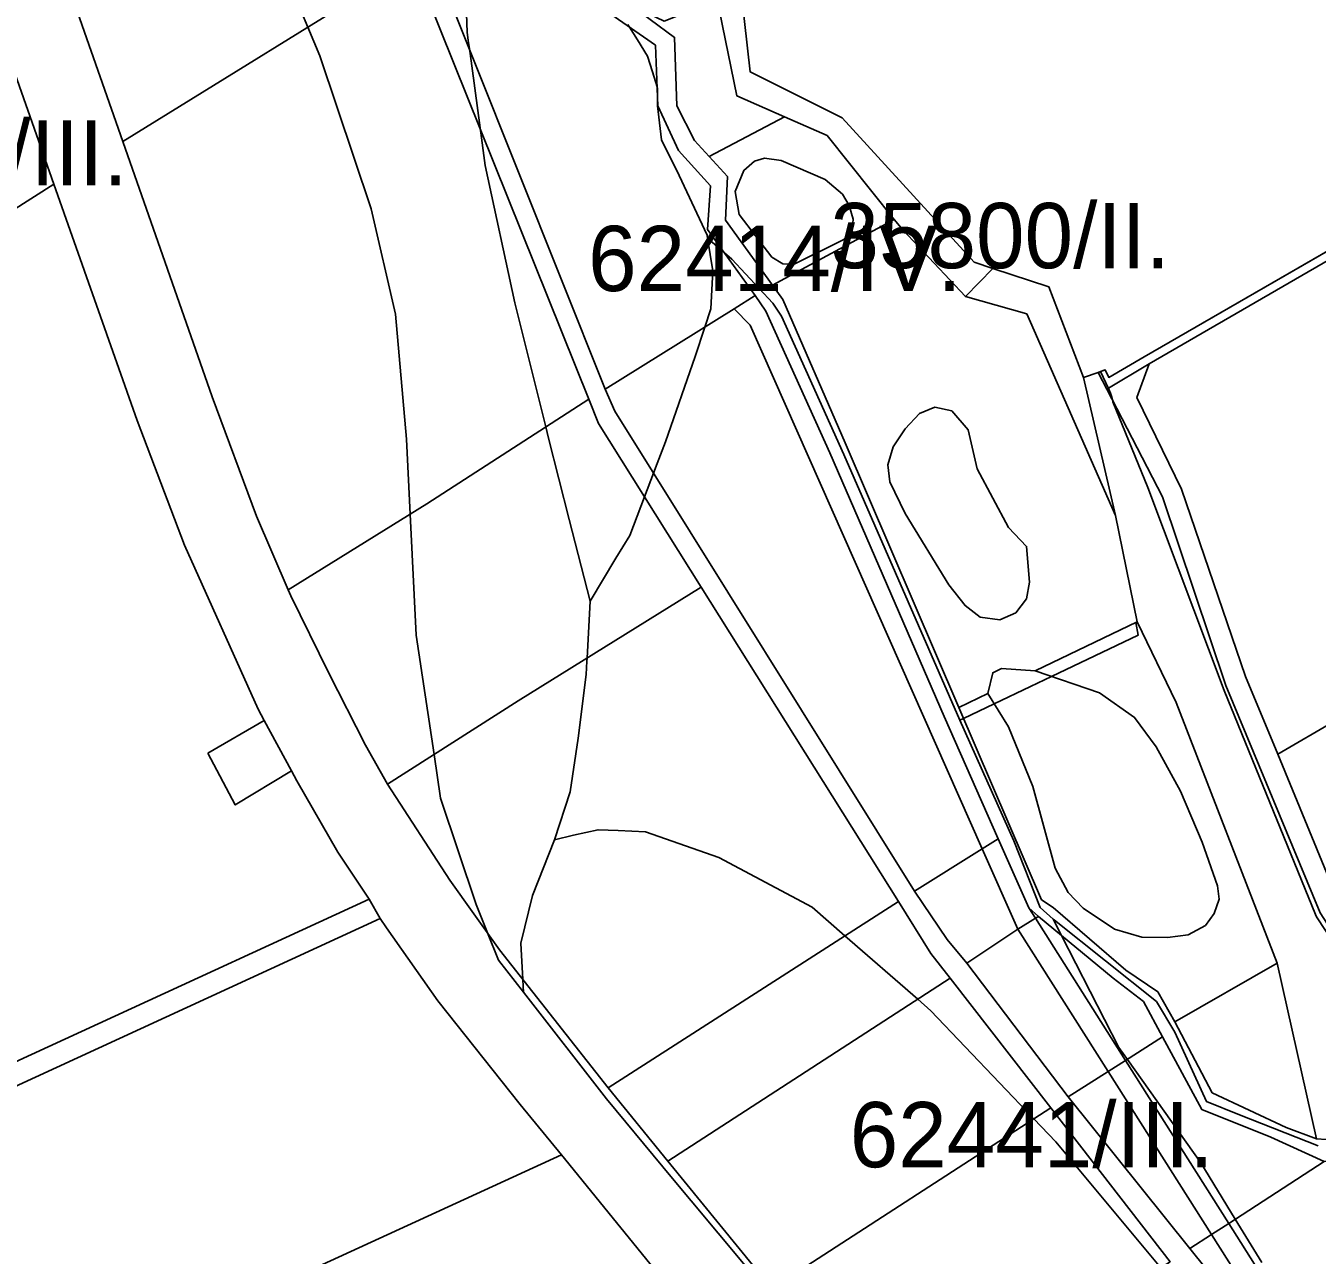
# Model space of a CAD drawing. Extents: x -522079 to -518792, y -1142400 to -1139961.
# Drawn here: x -520985.3 to -520688.5, y -1140520.9 to -1140238.4 of the extents above; entities that cross this region are included whole.
import ezdxf

# ---------------------------------------------------------------- set-up
doc = ezdxf.new("R2010")
doc.units = 0
for name, color, linetype in [('Hranice parcel', 7, 'Continuous'), ('Parcelní čísla', 7, 'Continuous'), ('Poz předměty', 7, 'Continuous'), ('Vnitřní kresba', 7, 'Continuous'), ('Značky bodu BP', 7, 'Continuous'), ('Značky budov', 7, 'Continuous')]:
    doc.layers.add(name, color=color, linetype=linetype)

msp = doc.modelspace()

# ---------------------------------------------------------------- linework, layer by layer
at = {"layer": 'Hranice parcel'}
for points in [[(-520489.41, -1140176.97), (-520610.57, -1140248.68), (-520727.12, -1140316.09), (-520736.79, -1140321.94), (-520738.8, -1140318.04), (-520737.2, -1140317.47), (-520736.37, -1140319.22), (-520728.21, -1140314.51), (-520611.62, -1140247.2), (-520491.09, -1140175.17)], [(-520989.57, -1140189.1), (-520981.4, -1140212.45), (-520975.5, -1140229.32), (-520963.03, -1140264.99), (-520942.5, -1140323.7), (-520932.27, -1140351.12), (-520925.04, -1140368.05), (-520924.44, -1140369.44), (-520915.77, -1140387.04), (-520907.24, -1140403.74), (-520902.19, -1140412.67), (-520887.82, -1140434.78), (-520876.46, -1140450.75), (-520851.49, -1140482.48), (-520837.71, -1140499.35), (-520813.81, -1140528.62)], [(-520765.71, -1140616.57), (-520862.22, -1140497.87), (-520871.65, -1140486.28), (-520890.58, -1140462.46), (-520902.4, -1140445.74), (-520903.84, -1140443.54), (-520906.37, -1140439.12), (-520913.58, -1140428.33), (-520923.06, -1140411.9), (-520924.28, -1140409.64), (-520930.52, -1140398.04), (-520931.92, -1140395.43), (-520948.85, -1140357.77), (-520959.74, -1140329.07), (-520978.89, -1140274.79), (-520991.34, -1140239.5)], [(-520560.63, -1140549.81), (-520611.7, -1140490.5), (-520625.05, -1140483.49), (-520666, -1140475.86), (-520687.78, -1140442.24), (-520709.46, -1140390.03), (-520724.04, -1140346.68), (-520736.79, -1140321.94), (-520727.12, -1140316.09), (-520729.96, -1140323.84), (-520719.64, -1140344.89), (-520704.93, -1140387.92), (-520697.54, -1140405.82), (-520683.48, -1140439.85), (-520673.87, -1140455.8), (-520666.98, -1140467.24), (-520659.41, -1140472.47), (-520623.97, -1140478.75), (-520608.7, -1140486.32), (-520592.52, -1140504.62), (-520587.65, -1140510.13), (-520562.49, -1140540.48)]]:
    msp.add_lwpolyline(points, dxfattribs=at)
for points in [[(-520822.46, -1140303.46), (-520817.67, -1140300.36), (-520815.23, -1140303.96), (-520800.48, -1140336.51), (-520774.21, -1140397.13), (-520761.78, -1140425.25), (-520765.49, -1140427.57), (-520818.84, -1140307.19)], [(-520943.46, -1140405.56), (-520930.52, -1140398.04), (-520924.28, -1140409.64), (-520937.19, -1140417.44)], [(-520754.76, -1140441.12), (-520753.24, -1140443.52), (-520757.32, -1140446.02), (-520765.49, -1140427.57), (-520761.78, -1140425.25)], [(-521428.47, -1140683.93), (-521438.02, -1140688.47), (-521441.99, -1140684.63), (-521355.48, -1140644.9), (-521309.07, -1140623.96), (-521152, -1140551.52), (-521060.49, -1140509.3), (-521045.09, -1140502.65), (-521031.07, -1140496.4), (-520906.37, -1140439.12), (-520903.84, -1140443.54), (-521038.29, -1140505.39), (-521174.07, -1140567.72), (-521187.8, -1140573.75), (-521306.81, -1140628.37)], [(-520757.32, -1140446.02), (-520753.24, -1140443.52), (-520732.54, -1140476.21), (-520736.54, -1140478.75)], [(-520721.21, -1140467.33), (-520697.67, -1140453.81), (-520688.63, -1140494.17), (-520695.64, -1140491.57), (-520712.6, -1140483.62)], [(-520732.54, -1140476.21), (-520708.82, -1140513.67), (-520712.75, -1140516.21), (-520736.54, -1140478.75)], [(-520708.82, -1140513.67), (-520688.32, -1140546.05), (-520692.27, -1140548.47), (-520712.75, -1140516.21)]]:
    msp.add_lwpolyline(points, close=True, dxfattribs=at)
at = {"layer": 'Parcelní čísla'}
for points in [[(-520697.54, -1140405.82), (-520704.93, -1140387.92), (-520719.64, -1140344.89), (-520729.96, -1140323.84), (-520727.12, -1140316.09), (-520610.57, -1140248.68), (-520489.41, -1140176.97), (-520443.64, -1140149.48), (-520437.53, -1140151.12), (-520407.86, -1140236.34), (-520563.45, -1140327.62)], [(-520896.25, -1140223.69), (-520963.03, -1140264.99), (-520975.5, -1140229.32), (-520909.48, -1140190.7)], [(-520863.77, -1140204.01), (-520859.87, -1140225.61), (-520850.88, -1140235.71), (-520840.6, -1140242.88), (-520840.04, -1140256.81), (-520835.3, -1140267.04), (-520827.93, -1140275.18), (-520828.6, -1140285.19), (-520817.67, -1140300.36), (-520822.46, -1140303.46), (-520852.13, -1140321.93), (-520892.27, -1140221.28)], [(-520963.03, -1140264.99), (-520896.25, -1140223.69), (-520855.89, -1140324.19), (-520893.13, -1140348.26), (-520925.04, -1140368.05), (-520932.27, -1140351.12), (-520942.5, -1140323.7)], [(-520407.86, -1140236.34), (-520389.24, -1140289.48), (-520535.21, -1140374.77), (-520673.87, -1140455.8), (-520683.48, -1140439.85), (-520697.54, -1140405.82), (-520563.45, -1140327.62)], [(-521144.75, -1140380.49), (-521166.55, -1140356.84), (-521138.04, -1140336), (-521105.44, -1140313.39), (-521071.25, -1140292.13), (-521029.36, -1140265.01), (-520991.34, -1140239.5), (-520978.89, -1140274.79)], [(-520943.46, -1140405.56), (-520937.19, -1140417.44), (-520924.28, -1140409.64), (-520923.06, -1140411.9), (-520913.58, -1140428.33), (-520906.37, -1140439.12), (-521031.07, -1140496.4), (-521039.03, -1140495.22), (-521144.75, -1140380.49), (-520978.89, -1140274.79), (-520959.74, -1140329.07), (-520948.85, -1140357.77), (-520931.92, -1140395.43), (-520930.52, -1140398.04)], [(-520853.68, -1140329.78), (-520830.07, -1140367.42), (-520872.15, -1140393.54), (-520902.19, -1140412.67), (-520907.24, -1140403.74), (-520915.77, -1140387.04), (-520924.44, -1140369.44), (-520925.04, -1140368.05), (-520893.13, -1140348.26), (-520855.89, -1140324.19)], [(-520781.06, -1140437.3), (-520765.49, -1140427.57), (-520757.32, -1140446.02), (-520769.04, -1140453.82), (-520773.55, -1140448.4)], [(-520851.49, -1140482.48), (-520784.75, -1140439.67), (-520777.25, -1140451.62), (-520772.84, -1140457.31), (-520837.71, -1140499.35)], [(-521174.07, -1140567.72), (-521038.29, -1140505.39), (-520903.84, -1140443.54), (-520902.4, -1140445.74), (-520890.58, -1140462.46), (-520871.65, -1140486.28), (-520862.22, -1140497.87), (-521134.28, -1140622.71), (-521175.11, -1140573.76)], [(-520757.32, -1140446.02), (-520736.54, -1140478.75), (-520745.68, -1140484.57), (-520769.04, -1140453.82)], [(-520837.71, -1140499.35), (-520772.84, -1140457.31), (-520749.72, -1140487.1), (-520813.81, -1140528.62)], [(-520736.54, -1140478.75), (-520712.75, -1140516.21), (-520717.71, -1140519.42), (-520745.68, -1140484.57)], [(-520785.9, -1140562.81), (-520813.81, -1140528.62), (-520749.72, -1140487.1), (-520722.28, -1140522.46), (-520735.82, -1140531.09)], [(-520862.22, -1140497.87), (-520765.71, -1140616.57), (-520897.82, -1140676.39), (-521036.95, -1140739.4), (-521134.28, -1140622.71)], [(-520712.75, -1140516.21), (-520692.27, -1140548.47), (-520693.7, -1140549.35), (-520717.71, -1140519.42)]]:
    msp.add_lwpolyline(points, close=True, dxfattribs=at)
msp.add_lwpolyline([(-520722.28, -1140522.46), (-520749.72, -1140487.1), (-520772.84, -1140457.31), (-520777.25, -1140451.62), (-520784.75, -1140439.67), (-520830.07, -1140367.42), (-520853.68, -1140329.78), (-520855.89, -1140324.19), (-520896.25, -1140223.69), (-520909.48, -1140190.7), (-520905.41, -1140188.32), (-520892.27, -1140221.28), (-520852.13, -1140321.93), (-520849.95, -1140326.96), (-520781.06, -1140437.3), (-520773.55, -1140448.4), (-520769.04, -1140453.82), (-520745.68, -1140484.57), (-520717.71, -1140519.42), (-520693.7, -1140549.35)], dxfattribs=at)
at = {"layer": 'Poz předměty'}
for points in [[(-520831.58, -1140264.76), (-520835.7, -1140256.78), (-520836.21, -1140241.05), (-520847.4, -1140232.82), (-520856.59, -1140222.67), (-520843.85, -1140234.81), (-520838.62, -1140237.3), (-520834.17, -1140235.54), (-520832.49, -1140233.14), (-520829.57, -1140196.57), (-520831.74, -1140193.15), (-520834.84, -1140193.48), (-520857.8, -1140202.58), (-520859.91, -1140204.51), (-520858.48, -1140201.26), (-520811.93, -1140174.77), (-520818.11, -1140203.91), (-520825.87, -1140235.03), (-520821.91, -1140254.48), (-520810.93, -1140259.32), (-520828.22, -1140268.46)], [(-520828.22, -1140268.46), (-520810.93, -1140259.32), (-520801.15, -1140263.64), (-520785.74, -1140282.9), (-520813.67, -1140297.99), (-520824.45, -1140283.03), (-520824.03, -1140273.06)], [(-520817.84, -1140269.53), (-520820.3, -1140271.64), (-520822.29, -1140276.46), (-520821.31, -1140281.75), (-520813.83, -1140291.57), (-520811.29, -1140293.11), (-520808.84, -1140293.29), (-520797.46, -1140287.61), (-520795.38, -1140285.61), (-520795.15, -1140282.87), (-520796.05, -1140279.66), (-520797.56, -1140277.1), (-520801.58, -1140273.72), (-520811.67, -1140269.37), (-520815.5, -1140268.8)], [(-520783.73, -1140285.25), (-520769.34, -1140300.61), (-520755.22, -1140304.57), (-520734.8, -1140350.95), (-520729.88, -1140375.38), (-520753.32, -1140386.65), (-520761.05, -1140386.08), (-520763.05, -1140387.08), (-520764.21, -1140391.88), (-520770.87, -1140395.08), (-520797.01, -1140334.21), (-520811.33, -1140301.33), (-520813.67, -1140297.99), (-520785.74, -1140282.9)], [(-520754.64, -1140366.29), (-520755.29, -1140358.03), (-520759.43, -1140353.7), (-520766.65, -1140340.21), (-520768.74, -1140331.28), (-520772.48, -1140326.88), (-520776.36, -1140326.07), (-520779.88, -1140327.47), (-520783.19, -1140331.06), (-520785.95, -1140335.16), (-520787.17, -1140339.26), (-520786.73, -1140343.23), (-520783.16, -1140350.46), (-520773.17, -1140366.91), (-520769.43, -1140371.66), (-520765.93, -1140374.29), (-520761.4, -1140374.89), (-520757.78, -1140373.33), (-520755.28, -1140370.09)], [(-520752.54, -1140443.09), (-520753.24, -1140443.52), (-520754.76, -1140441.12)], [(-520735.34, -1140457.3), (-520728.4, -1140462.65), (-520724, -1140470.78), (-520732.54, -1140476.21), (-520753.24, -1140443.52), (-520752.54, -1140443.09)], [(-520732.54, -1140476.21), (-520724, -1140470.78), (-520714.97, -1140487.48), (-520699.14, -1140493.81), (-520686.89, -1140499.45), (-520708.82, -1140513.67)], [(-520686.89, -1140499.45), (-520675.92, -1140498.77), (-520661.91, -1140491.42), (-520635.69, -1140488.94), (-520617.72, -1140496.63), (-520614.24, -1140500.69), (-520688.32, -1140546.05), (-520708.82, -1140513.67)]]:
    msp.add_lwpolyline(points, close=True, dxfattribs=at)
at = {"layer": 'Vnitřní kresba'}
for points in [[(-520821.47, -1140225.09), (-520818.83, -1140248.97), (-520797.63, -1140259.52), (-520767.33, -1140292.73), (-520763.01, -1140294.16), (-520769.34, -1140300.61), (-520783.73, -1140285.25), (-520785.74, -1140282.9), (-520801.15, -1140263.64), (-520810.93, -1140259.32), (-520821.91, -1140254.48), (-520825.87, -1140235.03)], [(-520847.4, -1140232.82), (-520836.21, -1140241.05), (-520835.7, -1140256.78), (-520831.58, -1140264.76), (-520828.22, -1140268.46), (-520824.03, -1140273.06), (-520824.45, -1140283.03), (-520813.67, -1140297.99), (-520811.33, -1140301.33), (-520797.01, -1140334.21), (-520770.87, -1140395.08), (-520751.81, -1140439.25), (-520749.19, -1140441.04), (-520732.44, -1140455.44), (-520725.07, -1140460.42), (-520721.21, -1140467.33), (-520712.6, -1140483.62), (-520695.64, -1140491.57), (-520688.63, -1140494.17), (-520677.55, -1140494.96)], [(-520686.89, -1140499.45), (-520699.14, -1140493.81), (-520714.97, -1140487.48), (-520724, -1140470.78), (-520728.4, -1140462.65), (-520735.34, -1140457.3), (-520752.54, -1140443.09), (-520754.76, -1140441.12), (-520761.78, -1140425.25), (-520774.21, -1140397.13), (-520800.48, -1140336.51), (-520815.23, -1140303.96), (-520817.67, -1140300.36), (-520828.6, -1140285.19), (-520827.93, -1140275.18), (-520835.3, -1140267.04), (-520840.04, -1140256.81), (-520840.6, -1140242.88), (-520850.88, -1140235.71)], [(-520677.55, -1140494.96), (-520688.63, -1140494.17), (-520697.67, -1140453.81), (-520720.9, -1140393.9), (-520729.88, -1140375.38), (-520734.8, -1140350.95), (-520755.22, -1140304.57), (-520769.34, -1140300.61), (-520763.01, -1140294.16), (-520750.13, -1140298.42), (-520742.16, -1140319.24), (-520738.8, -1140318.04), (-520736.79, -1140321.94), (-520724.04, -1140346.68), (-520709.46, -1140390.03), (-520687.78, -1140442.24)]]:
    msp.add_lwpolyline(points, dxfattribs=at)
for points in [[(-520795.15, -1140282.87), (-520795.38, -1140285.61), (-520797.46, -1140287.61), (-520808.84, -1140293.29), (-520811.29, -1140293.11), (-520813.83, -1140291.57), (-520821.31, -1140281.75), (-520822.29, -1140276.46), (-520820.3, -1140271.64), (-520817.84, -1140269.53), (-520815.5, -1140268.8), (-520811.67, -1140269.37), (-520801.58, -1140273.72), (-520797.56, -1140277.1), (-520796.05, -1140279.66)], [(-520768.74, -1140331.28), (-520766.65, -1140340.21), (-520759.43, -1140353.7), (-520755.29, -1140358.03), (-520754.64, -1140366.29), (-520755.28, -1140370.09), (-520757.78, -1140373.33), (-520761.4, -1140374.89), (-520765.93, -1140374.29), (-520769.43, -1140371.66), (-520773.17, -1140366.91), (-520783.16, -1140350.46), (-520786.73, -1140343.23), (-520787.17, -1140339.26), (-520785.95, -1140335.16), (-520783.19, -1140331.06), (-520779.88, -1140327.47), (-520776.36, -1140326.07), (-520772.48, -1140326.88)], [(-520729.88, -1140375.38), (-520720.9, -1140393.9), (-520697.67, -1140453.81), (-520721.21, -1140467.33), (-520725.07, -1140460.42), (-520732.44, -1140455.44), (-520749.19, -1140441.04), (-520751.81, -1140439.25), (-520770.87, -1140395.08), (-520764.21, -1140391.88), (-520759.4, -1140399.48), (-520753.83, -1140413.22), (-520748.72, -1140432.03), (-520745.71, -1140437.58), (-520742.3, -1140441.21), (-520735.07, -1140445.99), (-520728.76, -1140447.85), (-520722.88, -1140447.92), (-520718.16, -1140447.28), (-520714.17, -1140445.14), (-520712.14, -1140442.41), (-520711.04, -1140439.09), (-520711.41, -1140436.09), (-520714.9, -1140426), (-520719.87, -1140414.3), (-520725.51, -1140404.14), (-520730.43, -1140397.36), (-520738.54, -1140391.69), (-520753.32, -1140386.65)], [(-520753.32, -1140386.65), (-520738.54, -1140391.69), (-520730.43, -1140397.36), (-520725.51, -1140404.14), (-520719.87, -1140414.3), (-520714.9, -1140426), (-520711.41, -1140436.09), (-520711.04, -1140439.09), (-520712.14, -1140442.41), (-520714.17, -1140445.14), (-520718.16, -1140447.28), (-520722.88, -1140447.92), (-520728.76, -1140447.85), (-520735.07, -1140445.99), (-520742.3, -1140441.21), (-520745.71, -1140437.58), (-520748.72, -1140432.03), (-520753.83, -1140413.22), (-520759.4, -1140399.48), (-520764.21, -1140391.88), (-520763.05, -1140387.08), (-520761.05, -1140386.08)]]:
    msp.add_lwpolyline(points, close=True, dxfattribs=at)
at = {"layer": 'Značky bodu BP'}
for points in [[(-520884.7, -1140216.69), (-520883.86, -1140239.89), (-520883.61, -1140241.74), (-520883.37, -1140243.6), (-520880.92, -1140261.86), (-520879.76, -1140270.51), (-520872.93, -1140302.05), (-520865.81, -1140330.6), (-520865.18, -1140333.13), (-520860.4, -1140351.86), (-520855.62, -1140370.6), (-520856.32, -1140383.71), (-520856.36, -1140384.4), (-520856.53, -1140387.51), (-520858.35, -1140402.14), (-520860.17, -1140414.48), (-520863.82, -1140425.45), (-520868.83, -1140438.25), (-520871.56, -1140449.22), (-520871.11, -1140457.55), (-520871.02, -1140459.15), (-520870.94, -1140460.53), (-520876.68, -1140453.17), (-520879.22, -1140446.87), (-520881.84, -1140440.36), (-520889.98, -1140415.87), (-520891.48, -1140405.85), (-520895.59, -1140378.43), (-520896.97, -1140350.64), (-520897.83, -1140333.39), (-520900.36, -1140304.68), (-520905.97, -1140280.47), (-520917.76, -1140245.28), (-520920.51, -1140238.69), (-520931.79, -1140211.78)], [(-520931.79, -1140211.78), (-520920.51, -1140238.69), (-520917.76, -1140245.28), (-520905.97, -1140280.47), (-520900.36, -1140304.68), (-520897.83, -1140333.39), (-520896.97, -1140350.64), (-520895.59, -1140378.43), (-520891.48, -1140405.85), (-520889.98, -1140415.87), (-520881.84, -1140440.36), (-520879.22, -1140446.87), (-520876.68, -1140453.17), (-520870.94, -1140460.53), (-520851.87, -1140485.02), (-520838.89, -1140500.65), (-520838.57, -1140501.03), (-520819.98, -1140523.33)], [(-520846.96, -1140238.06), (-520846.54, -1140238.74), (-520844.73, -1140241.63), (-520842.4, -1140245.37), (-520841.27, -1140249.01), (-520840.22, -1140252.39), (-520840.17, -1140252.54), (-520840.12, -1140252.69), (-520840.12, -1140254.69), (-520840.12, -1140256.8), (-520839.21, -1140264.57), (-520835.11, -1140272.8), (-520828.73, -1140286.51), (-520828.62, -1140287.17), (-520827.37, -1140294.74), (-520827.82, -1140303.42), (-520829.24, -1140307.68), (-520831.47, -1140314.39), (-520838.3, -1140334.04), (-520840.19, -1140338.98), (-520841.04, -1140341.23), (-520843.11, -1140346.63), (-520846.5, -1140355.52), (-520849.66, -1140360.74), (-520855.62, -1140370.6), (-520860.4, -1140351.86), (-520865.18, -1140333.13), (-520865.81, -1140330.6), (-520872.93, -1140302.05), (-520879.76, -1140270.51), (-520880.92, -1140261.86), (-520883.37, -1140243.6), (-520883.61, -1140241.74), (-520883.86, -1140239.89), (-520884.7, -1140216.69)], [(-520821.47, -1140225.09), (-520818.83, -1140248.97), (-520797.63, -1140259.52), (-520767.33, -1140292.73), (-520763.01, -1140294.16), (-520750.13, -1140298.42), (-520742.16, -1140319.24), (-520734.8, -1140350.95), (-520729.88, -1140375.38), (-520730.16, -1140375.51), (-520729.61, -1140378.41), (-520749.55, -1140387.93), (-520754.34, -1140390.21), (-520762.73, -1140394.22), (-520769.79, -1140397.59), (-520770.64, -1140398), (-520797.28, -1140336.9), (-520811.58, -1140305.16), (-520813.62, -1140302.12), (-520823.03, -1140292.05), (-520824.71, -1140290.58), (-520828.62, -1140287.17), (-520828.73, -1140286.51), (-520835.11, -1140272.8), (-520839.21, -1140264.57), (-520840.12, -1140256.8), (-520840.12, -1140254.69), (-520840.12, -1140252.69), (-520840.17, -1140252.54), (-520840.22, -1140252.39), (-520841.27, -1140249.01), (-520842.4, -1140245.37), (-520844.73, -1140241.63), (-520846.54, -1140238.74), (-520846.96, -1140238.06)], [(-520666.58, -1140476.66), (-520688.6, -1140443.21), (-520688.85, -1140442.65), (-520709.83, -1140391.18), (-520727.37, -1140344.51), (-520735.41, -1140324.82), (-520735.53, -1140324.37), (-520735.77, -1140323.51), (-520735.96, -1140322.84), (-520736.47, -1140321.75), (-520738.3, -1140317.86), (-520737.2, -1140317.47), (-520736.37, -1140319.22), (-520728.21, -1140314.51), (-520679.51, -1140286.39)], [(-520724.41, -1140523.82), (-520748.55, -1140494.92), (-520753.6, -1140489.61), (-520777.25, -1140464.76), (-520780.27, -1140462.13), (-520797.04, -1140447.55), (-520804.59, -1140440.99), (-520826, -1140429.57), (-520835.24, -1140426.31), (-520842.86, -1140423.62), (-520849.16, -1140423.36), (-520853.79, -1140423.17), (-520859.39, -1140424.44), (-520863.82, -1140425.45), (-520860.17, -1140414.48), (-520858.35, -1140402.14), (-520856.53, -1140387.51), (-520856.36, -1140384.4), (-520856.32, -1140383.71), (-520855.62, -1140370.6), (-520849.66, -1140360.74), (-520846.5, -1140355.52), (-520843.11, -1140346.63), (-520841.04, -1140341.23), (-520840.19, -1140338.98), (-520838.3, -1140334.04), (-520831.47, -1140314.39), (-520829.24, -1140307.68), (-520827.82, -1140303.42), (-520827.37, -1140294.74), (-520828.62, -1140287.17), (-520824.71, -1140290.58), (-520823.03, -1140292.05), (-520813.62, -1140302.12), (-520811.58, -1140305.16), (-520797.28, -1140336.9), (-520770.64, -1140398), (-520758.19, -1140425.7), (-520752.15, -1140441.01), (-520749.16, -1140443.69), (-520747.22, -1140447.48), (-520734.04, -1140473.22), (-520732.11, -1140475.94), (-520715.23, -1140499.75), (-520707.3, -1140512.68), (-520701.19, -1140522.65)], [(-520688.28, -1140495.8), (-520706.32, -1140488.67), (-520713.93, -1140485.66), (-520716.78, -1140479.4), (-520721.2, -1140469.67), (-520725.4, -1140462.65), (-520748.84, -1140443.98), (-520749.16, -1140443.69), (-520752.15, -1140441.01), (-520758.19, -1140425.7), (-520770.64, -1140398), (-520769.79, -1140397.59), (-520762.73, -1140394.22), (-520754.34, -1140390.21), (-520749.55, -1140387.93), (-520729.61, -1140378.41), (-520730.16, -1140375.51), (-520729.88, -1140375.38), (-520734.8, -1140350.95), (-520742.16, -1140319.24), (-520738.8, -1140318.04), (-520738.3, -1140317.86), (-520736.47, -1140321.75), (-520735.96, -1140322.84), (-520735.77, -1140323.51), (-520735.53, -1140324.37), (-520735.41, -1140324.82), (-520727.37, -1140344.51), (-520709.83, -1140391.18), (-520688.85, -1140442.65), (-520688.6, -1140443.21), (-520666.58, -1140476.66)], [(-520819.98, -1140523.33), (-520838.57, -1140501.03), (-520838.89, -1140500.65), (-520851.87, -1140485.02), (-520870.94, -1140460.53), (-520871.02, -1140459.15), (-520871.11, -1140457.55), (-520871.56, -1140449.22), (-520868.83, -1140438.25), (-520863.82, -1140425.45), (-520859.39, -1140424.44), (-520853.79, -1140423.17), (-520849.16, -1140423.36), (-520842.86, -1140423.62), (-520835.24, -1140426.31), (-520826, -1140429.57), (-520804.59, -1140440.99), (-520797.04, -1140447.55), (-520780.27, -1140462.13), (-520777.25, -1140464.76), (-520753.6, -1140489.61), (-520748.55, -1140494.92), (-520724.41, -1140523.82)], [(-520701.19, -1140522.65), (-520707.3, -1140512.68), (-520715.23, -1140499.75), (-520732.11, -1140475.94), (-520734.04, -1140473.22), (-520747.22, -1140447.48), (-520749.16, -1140443.69), (-520748.84, -1140443.98), (-520725.4, -1140462.65), (-520721.2, -1140469.67), (-520716.78, -1140479.4), (-520713.93, -1140485.66), (-520706.32, -1140488.67), (-520688.28, -1140495.8)]]:
    msp.add_lwpolyline(points, dxfattribs=at)
at = {"layer": 'Značky budov'}
for points in [[(-520849.95, -1140326.96), (-520852.13, -1140321.93), (-520822.46, -1140303.46), (-520818.84, -1140307.19), (-520765.49, -1140427.57), (-520781.06, -1140437.3)], [(-520902.19, -1140412.67), (-520872.15, -1140393.54), (-520830.07, -1140367.42), (-520784.75, -1140439.67), (-520851.49, -1140482.48), (-520876.46, -1140450.75), (-520887.82, -1140434.78)]]:
    msp.add_lwpolyline(points, close=True, dxfattribs=at)

# ---------------------------------------------------------------- texts
at = {"layer": 'Značky bodu BP'}
msp.add_text('61450/III.', height=15, dxfattribs=at).set_placement((-521045.59, -1140275.09))
for s, rotation, p in [('35800/II.', 360, (-520800.36, -1140294.11)), ('62414/IV.', 0, (-520856.07, -1140299.36)), ('62441/III.', 360, (-520795.93, -1140500.74))]:
    msp.add_text(s, height=15, rotation=rotation, dxfattribs=at).set_placement(p)

doc.saveas('drawing.dxf')
